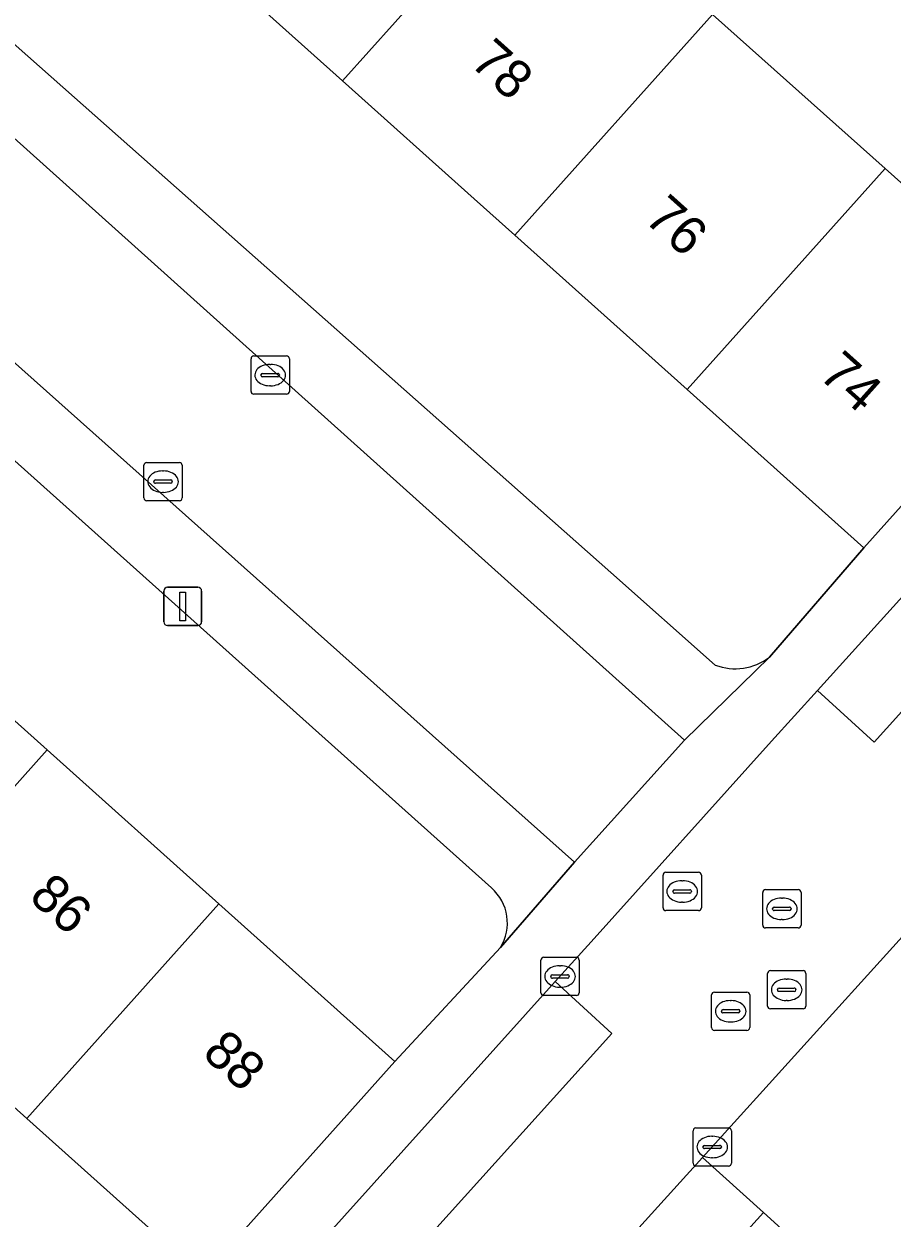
# Model space of a CAD drawing. Extents: x 159039 to 160102, y 381214 to 382524.
# Drawn here: x 159488.23 to 159510.93, y 381770.5 to 381801.71 of the extents above; entities that cross this region are included whole.
import ezdxf

# ---------------------------------------------------------------- set-up
doc = ezdxf.new("R2010")
doc.units = 0
for name, color, linetype in [('IMGEO_Erf', 7, 'Continuous'), ('IMGEO_Kolk', 7, 'Continuous'), ('IMGEO_Lichtmast', 7, 'Continuous'), ('IMGEO_Pand', 7, 'Continuous'), ('IMGEO_Pand_nummerreeks', 7, 'Continuous'), ('IMGEO_Parkeervlak_open', 7, 'Continuous'), ('IMGEO_Rijbaan_lokaal_open', 7, 'Continuous'), ('IMGEO_Rioolput', 7, 'Continuous'), ('IMGEO_Voetpad_open', 7, 'Continuous')]:
    doc.layers.add(name, color=color, linetype=linetype)

msp = doc.modelspace()

# ---------------------------------------------------------------- linework, layer by layer
at = {"layer": 'IMGEO_Erf'}
for points in [[(159500, 381819.846), (159495.918, 381815.23), (159500, 381811.574), (159503.673, 381808.285), (159503.333, 381807.906), (159503.451, 381807.8), (159507.898, 381803.818), (159506.231, 381801.957), (159510.743, 381797.929), (159515.367, 381793.8)], [(159501.065, 381796.188), (159500, 381797.141), (159496.559, 381800.223), (159491.947, 381804.353), (159492.348, 381804.8), (159489.145, 381807.669), (159485.386, 381803.473), (159485.533, 381803.343), (159487.723, 381801.404), (159503.573, 381787.369), (159506.301, 381784.953)], [(159500.454, 381779.131), (159482.304, 381795.376), (159480.705, 381796.807), (159481.965, 381798.214), (159482.586, 381798.907), (159481.405, 381800.01), (159470.575, 381788.888), (159462.202, 381778.537), (159461.61, 381777.805), (159456.183, 381771.095), (159456.944, 381770.48)], [(159507.718, 381785.16), (159510.188, 381788.017), (159505.57, 381792.153), (159501.065, 381796.188)], [(159473.576, 381783.985), (159474.721, 381785.263), (159472.259, 381787.467), (159476.579, 381792.296), (159479.045, 381790.089), (159479.818, 381790.953), (159480.34, 381790.486), (159484.353, 381786.758), (159488.841, 381782.739), (159493.329, 381778.719), (159497.93, 381774.598), (159500.688, 381777.572)], [(159492.904, 381768.986), (159488.306, 381773.102), (159483.817, 381777.121), (159481.709, 381774.763), (159477.218, 381778.778)]]:
    msp.add_lwpolyline(points, dxfattribs=at)
msp.add_lwpolyline([(159503.851, 381765.543), (159508.032, 381770.22), (159507.563, 381770.646), (159495.232, 381757.035), (159495.792, 381756.528), (159499.772, 381760.98), (159500, 381761.235)], close=True, dxfattribs=at)
for centre, radius, start, end in [((159506.824, 381786.328), 1.471, 249.1896, 307.4328), ((159499.643, 381778.212), 1.225, 328.5016, 48.5707)]:
    msp.add_arc(centre, radius, start, end, dxfattribs=at)
at = {"layer": 'IMGEO_Kolk'}
for p, q in [((159494.167, 381792.106), (159494.167, 381792.958)), ((159494.242, 381793.032), (159495.094, 381793.032)), ((159494.655, 381792.812), (159494.68, 381792.812)), ((159495.168, 381792.958), (159495.168, 381792.106)), ((159494.426, 381792.526), (159494.426, 381792.538)), ((159494.864, 381792.489), (159494.466, 381792.489)), ((159494.469, 381792.575), (159494.867, 381792.575)), ((159494.91, 381792.538), (159494.91, 381792.526)), ((159494.678, 381792.252), (159494.653, 381792.252)), ((159495.094, 381792.032), (159494.242, 381792.032)), ((159491.366, 381789.321), (159491.366, 381790.173)), ((159491.441, 381790.247), (159492.293, 381790.247)), ((159491.854, 381790.027), (159491.879, 381790.027)), ((159492.367, 381790.173), (159492.367, 381789.321)), ((159491.625, 381789.741), (159491.625, 381789.753)), ((159492.063, 381789.704), (159491.665, 381789.704)), ((159491.668, 381789.79), (159492.066, 381789.79)), ((159492.109, 381789.753), (159492.109, 381789.741)), ((159491.877, 381789.467), (159491.852, 381789.467)), ((159492.293, 381789.247), (159491.441, 381789.247)), ((159501.744, 381776.392), (159501.744, 381777.244)), ((159501.819, 381777.318), (159502.671, 381777.318)), ((159502.745, 381777.244), (159502.745, 381776.392)), ((159502.046, 381776.861), (159502.444, 381776.861)), ((159502.232, 381777.098), (159502.257, 381777.098)), ((159502.003, 381776.812), (159502.003, 381776.824)), ((159502.441, 381776.775), (159502.043, 381776.775)), ((159502.255, 381776.538), (159502.23, 381776.538)), ((159502.487, 381776.824), (159502.487, 381776.812)), ((159502.671, 381776.318), (159501.819, 381776.318)), ((159505.722, 381771.935), (159505.722, 381772.787)), ((159505.797, 381772.861), (159506.649, 381772.861)), ((159506.723, 381772.787), (159506.723, 381771.935)), ((159506.21, 381772.641), (159506.235, 381772.641)), ((159505.981, 381772.355), (159505.981, 381772.367)), ((159506.419, 381772.318), (159506.021, 381772.318)), ((159506.024, 381772.404), (159506.422, 381772.404)), ((159506.465, 381772.367), (159506.465, 381772.355)), ((159506.649, 381771.861), (159505.797, 381771.861)), ((159506.233, 381772.081), (159506.208, 381772.081))]:
    msp.add_line(p, q, dxfattribs=at)
for points in [[(159494.167, 381792.106), (159494.167, 381792.958)], [(159494.242, 381793.032), (159495.094, 381793.032)], [(159495.168, 381792.958), (159495.168, 381792.106)], [(159495.094, 381792.032), (159494.242, 381792.032)], [(159491.366, 381789.321), (159491.366, 381790.173)], [(159491.441, 381790.247), (159492.293, 381790.247)], [(159492.367, 381790.173), (159492.367, 381789.321)], [(159492.293, 381789.247), (159491.441, 381789.247)], [(159501.744, 381776.392), (159501.744, 381777.244)], [(159501.819, 381777.318), (159502.671, 381777.318)], [(159502.745, 381777.244), (159502.745, 381776.392)], [(159502.671, 381776.318), (159501.819, 381776.318)], [(159505.722, 381771.935), (159505.722, 381772.787)], [(159505.797, 381772.861), (159506.649, 381772.861)], [(159506.723, 381772.787), (159506.723, 381771.935)], [(159506.649, 381771.861), (159505.797, 381771.861)]]:
    msp.add_lwpolyline(points, dxfattribs=at)
for centre, radius, start, end in [((159494.244, 381792.956), 0.0765, 91.552, 178.448), ((159494.244, 381792.956), 0.0765, 91.552, 178.448), ((159495.092, 381792.956), 0.0765, 1.552, 88.448), ((159495.092, 381792.956), 0.0765, 1.552, 88.448), ((159494.466, 381792.535), 0.0403, 85.8775, 175.7526), ((159494.463, 381792.525), 0.0366, 178.938, 274.7102), ((159494.867, 381792.532), 0.043, 264.8664, 352.4533), ((159494.871, 381792.537), 0.0386, 1.7309, 96.639), ((159494.244, 381792.108), 0.0765, 181.552, 268.448), ((159494.244, 381792.108), 0.0765, 181.552, 268.448), ((159495.092, 381792.108), 0.0765, 271.552, 358.448), ((159495.092, 381792.108), 0.0765, 271.552, 358.448), ((159491.443, 381790.171), 0.0765, 91.552, 178.448), ((159491.443, 381790.171), 0.0765, 91.552, 178.448), ((159492.291, 381790.171), 0.0765, 1.552, 88.448), ((159492.291, 381790.171), 0.0765, 1.552, 88.448), ((159491.665, 381789.75), 0.0403, 85.8775, 175.7526), ((159491.662, 381789.74), 0.0366, 178.938, 274.7102), ((159492.066, 381789.747), 0.043, 264.8664, 352.4533), ((159492.07, 381789.752), 0.0386, 1.7309, 96.639), ((159491.443, 381789.323), 0.0765, 181.552, 268.448), ((159491.443, 381789.323), 0.0765, 181.552, 268.448), ((159492.291, 381789.323), 0.0765, 271.552, 358.448), ((159492.291, 381789.323), 0.0765, 271.552, 358.448), ((159501.821, 381777.242), 0.0765, 91.552, 178.448), ((159501.821, 381777.242), 0.0765, 91.552, 178.448), ((159502.669, 381777.242), 0.0765, 1.552, 88.448), ((159502.669, 381777.242), 0.0765, 1.552, 88.448), ((159502.043, 381776.821), 0.0403, 85.8775, 175.7526), ((159502.448, 381776.823), 0.0386, 1.7309, 96.639), ((159502.04, 381776.811), 0.0366, 178.938, 274.7102), ((159502.444, 381776.818), 0.043, 264.8664, 352.4533), ((159501.821, 381776.394), 0.0765, 181.552, 268.448), ((159501.821, 381776.394), 0.0765, 181.552, 268.448), ((159502.669, 381776.394), 0.0765, 271.552, 358.448), ((159502.669, 381776.394), 0.0765, 271.552, 358.448), ((159505.799, 381772.785), 0.0765, 91.552, 178.448), ((159505.799, 381772.785), 0.0765, 91.552, 178.448), ((159506.647, 381772.785), 0.0765, 1.552, 88.448), ((159506.647, 381772.785), 0.0765, 1.552, 88.448), ((159506.021, 381772.364), 0.0403, 85.8775, 175.7526), ((159506.018, 381772.354), 0.0366, 178.938, 274.7102), ((159506.422, 381772.361), 0.043, 264.8664, 352.4533), ((159506.426, 381772.366), 0.0386, 1.7309, 96.639), ((159505.799, 381771.937), 0.0765, 181.552, 268.448), ((159505.799, 381771.937), 0.0765, 181.552, 268.448), ((159506.647, 381771.937), 0.0765, 271.552, 358.448), ((159506.647, 381771.937), 0.0765, 271.552, 358.448)]:
    msp.add_arc(centre, radius, start, end, dxfattribs=at)
for centre, major_axis, ratio, start_param, end_param in [((159494.654, 381792.532), (-0.387, 0.002), 0.722429, 4.712389, 7.853982), ((159494.679, 381792.532), (-0.39, 0.002), 0.717154, 1.570796, 4.712389), ((159491.853, 381789.747), (-0.387, 0.002), 0.722429, 4.712389, 7.853982), ((159491.878, 381789.747), (-0.39, 0.002), 0.717154, 1.570796, 4.712389), ((159502.231, 381776.818), (-0.387, 0.002), 0.722429, 4.712389, 7.853982), ((159502.256, 381776.818), (-0.39, 0.002), 0.717154, 1.570796, 4.712389), ((159506.209, 381772.361), (-0.387, 0.002), 0.722429, 4.712389, 7.853982), ((159506.234, 381772.361), (-0.39, 0.002), 0.717154, 1.570796, 4.712389)]:
    msp.add_ellipse(centre, major_axis=major_axis, ratio=ratio, start_param=start_param, end_param=end_param, dxfattribs=at)
at = {"layer": 'IMGEO_Lichtmast'}
for p, q in [((159491.886, 381786.086), (159491.886, 381786.886)), ((159491.886, 381786.886), (159491.886, 381786.086)), ((159491.986, 381786.986), (159492.776, 381786.986)), ((159492.776, 381786.986), (159491.986, 381786.986)), ((159492.876, 381786.886), (159492.876, 381786.086)), ((159492.876, 381786.086), (159492.876, 381786.886)), ((159492.776, 381785.986), (159491.986, 381785.986)), ((159491.986, 381785.986), (159492.776, 381785.986))]:
    msp.add_line(p, q, dxfattribs=at)
msp.add_lwpolyline([(159492.306, 381786.861), (159492.456, 381786.861), (159492.456, 381786.111), (159492.306, 381786.111), (159492.306, 381786.861)], dxfattribs=at)
for centre, start, end in [((159491.986, 381786.886), 90, 180), ((159491.986, 381786.886), 90, 180), ((159492.776, 381786.886), 0, 90), ((159492.776, 381786.886), 360, 90), ((159491.986, 381786.086), 180, 270), ((159491.986, 381786.086), 180, 270), ((159492.776, 381786.086), 270, 0), ((159492.776, 381786.086), 270, 0)]:
    msp.add_arc(centre, 0.1, start, end, dxfattribs=at)
at = {"layer": 'IMGEO_Pand'}
for points in [[(159496.559, 381800.223), (159500, 381804.065), (159501.736, 381806.004), (159503.451, 381807.8), (159503.333, 381807.906), (159503.673, 381808.285), (159500, 381811.574), (159495.918, 381815.23), (159489.145, 381807.669), (159492.348, 381804.8), (159491.947, 381804.353)], [(159496.559, 381800.223), (159500, 381797.141), (159501.065, 381796.188), (159506.231, 381801.957), (159507.898, 381803.818), (159503.451, 381807.8), (159501.736, 381806.004), (159500, 381804.065)], [(159510.743, 381797.929), (159506.231, 381801.957), (159501.065, 381796.188), (159505.57, 381792.153)], [(159510.743, 381797.929), (159505.57, 381792.153), (159510.188, 381788.017), (159515.367, 381793.8)], [(159488.841, 381782.739), (159484.353, 381786.758), (159479.328, 381781.139), (159477.218, 381778.778), (159481.709, 381774.763), (159483.817, 381777.121)], [(159493.329, 381778.719), (159488.841, 381782.739), (159483.817, 381777.121), (159488.306, 381773.102)], [(159493.329, 381778.719), (159488.306, 381773.102), (159492.904, 381768.986), (159497.93, 381774.598)]]:
    msp.add_lwpolyline(points, close=True, dxfattribs=at)
at = {"layer": 'IMGEO_Parkeervlak_open'}
for points in [[(159520.178, 381796.676), (159508.977, 381784.292), (159510.46, 381782.935), (159521.64, 381795.325)], [(159502.12, 381776.684), (159490.252, 381763.489), (159491.718, 381762.164), (159503.595, 381775.326)]]:
    msp.add_lwpolyline(points, close=True, dxfattribs=at)
msp.add_lwpolyline([(159491.728, 381753.174), (159494.123, 381755.811), (159495.232, 381757.035), (159507.563, 381770.646), (159505.968, 381772.09), (159492.635, 381757.366), (159490.12, 381754.579), (159488.97, 381753.299), (159485.771, 381749.749), (159479.731, 381743.038)], dxfattribs=at)
at = {"layer": 'IMGEO_Rijbaan_lokaal_open'}
msp.add_lwpolyline([(159492.635, 381757.366), (159505.968, 381772.09), (159511.108, 381777.766), (159533.847, 381802.894), (159530.884, 381805.57), (159529.238, 381803.745), (159527.763, 381805.071), (159527.126, 381804.363), (159521.088, 381797.682), (159520.178, 381796.676), (159521.64, 381795.325), (159510.46, 381782.935), (159508.977, 381784.292), (159507.773, 381782.961), (159503.057, 381777.726), (159502.12, 381776.684), (159503.595, 381775.326), (159491.718, 381762.164)], dxfattribs=at)
msp.add_lwpolyline([(159486.504, 381800.037), (159484.913, 381801.464), (159484.376, 381800.892), (159482.586, 381798.907), (159481.965, 381798.214), (159483.564, 381796.789), (159502.62, 381779.807), (159504.061, 381781.401), (159505.502, 381782.995)], close=True, dxfattribs=at)
at = {"layer": 'IMGEO_Rioolput'}
for p, q in [((159504.937, 381778.613), (159504.937, 381779.465)), ((159505.012, 381779.539), (159505.864, 381779.539)), ((159505.938, 381779.465), (159505.938, 381778.613)), ((159505.196, 381779.033), (159505.196, 381779.045)), ((159505.239, 381779.082), (159505.637, 381779.082)), ((159505.425, 381779.319), (159505.45, 381779.319)), ((159505.68, 381779.045), (159505.68, 381779.033)), ((159507.618, 381779.085), (159508.47, 381779.085)), ((159505.634, 381778.996), (159505.236, 381778.996)), ((159505.448, 381778.759), (159505.423, 381778.759)), ((159507.543, 381778.159), (159507.543, 381779.011)), ((159508.031, 381778.865), (159508.056, 381778.865)), ((159508.544, 381779.011), (159508.544, 381778.159)), ((159505.864, 381778.539), (159505.012, 381778.539)), ((159507.802, 381778.579), (159507.802, 381778.591)), ((159508.24, 381778.542), (159507.842, 381778.542)), ((159507.845, 381778.628), (159508.243, 381778.628)), ((159508.286, 381778.591), (159508.286, 381778.579)), ((159508.47, 381778.085), (159507.618, 381778.085)), ((159508.054, 381778.305), (159508.029, 381778.305)), ((159507.669, 381776.044), (159507.669, 381776.896)), ((159507.744, 381776.97), (159508.596, 381776.97)), ((159508.67, 381776.896), (159508.67, 381776.044)), ((159508.157, 381776.75), (159508.182, 381776.75)), ((159506.204, 381775.481), (159506.204, 381776.333)), ((159506.279, 381776.407), (159507.131, 381776.407)), ((159507.205, 381776.333), (159507.205, 381775.481)), ((159507.928, 381776.464), (159507.928, 381776.476)), ((159508.366, 381776.427), (159507.968, 381776.427)), ((159507.971, 381776.513), (159508.369, 381776.513)), ((159508.412, 381776.476), (159508.412, 381776.464)), ((159506.463, 381775.901), (159506.463, 381775.913)), ((159506.506, 381775.95), (159506.904, 381775.95)), ((159506.692, 381776.187), (159506.717, 381776.187)), ((159506.947, 381775.913), (159506.947, 381775.901)), ((159508.596, 381775.97), (159507.744, 381775.97)), ((159508.18, 381776.19), (159508.155, 381776.19)), ((159506.901, 381775.864), (159506.503, 381775.864)), ((159506.715, 381775.627), (159506.69, 381775.627)), ((159507.131, 381775.407), (159506.279, 381775.407))]:
    msp.add_line(p, q, dxfattribs=at)
for points in [[(159504.937, 381778.613), (159504.937, 381779.465)], [(159505.012, 381779.539), (159505.864, 381779.539)], [(159505.938, 381779.465), (159505.938, 381778.613)], [(159507.618, 381779.085), (159508.47, 381779.085)], [(159507.543, 381778.159), (159507.543, 381779.011)], [(159508.544, 381779.011), (159508.544, 381778.159)], [(159505.864, 381778.539), (159505.012, 381778.539)], [(159508.47, 381778.085), (159507.618, 381778.085)], [(159507.669, 381776.044), (159507.669, 381776.896)], [(159507.744, 381776.97), (159508.596, 381776.97)], [(159508.67, 381776.896), (159508.67, 381776.044)], [(159506.204, 381775.481), (159506.204, 381776.333)], [(159506.279, 381776.407), (159507.131, 381776.407)], [(159507.205, 381776.333), (159507.205, 381775.481)], [(159508.596, 381775.97), (159507.744, 381775.97)], [(159507.131, 381775.407), (159506.279, 381775.407)]]:
    msp.add_lwpolyline(points, dxfattribs=at)
for centre, radius, start, end in [((159505.014, 381779.463), 0.0765, 91.552, 178.448), ((159505.014, 381779.463), 0.0765, 91.552, 178.448), ((159505.862, 381779.463), 0.0765, 1.552, 88.448), ((159505.862, 381779.463), 0.0765, 1.552, 88.448), ((159505.236, 381779.042), 0.0403, 85.8775, 175.7526), ((159505.233, 381779.032), 0.0366, 178.938, 274.7102), ((159505.637, 381779.039), 0.043, 264.8664, 352.4533), ((159505.641, 381779.044), 0.0386, 1.7309, 96.639), ((159507.62, 381779.009), 0.0765, 91.552, 178.448), ((159507.62, 381779.009), 0.0765, 91.552, 178.448), ((159508.468, 381779.009), 0.0765, 1.552, 88.448), ((159508.468, 381779.009), 0.0765, 1.552, 88.448), ((159505.014, 381778.615), 0.0765, 181.552, 268.448), ((159505.014, 381778.615), 0.0765, 181.552, 268.448), ((159505.862, 381778.615), 0.0765, 271.552, 358.448), ((159505.862, 381778.615), 0.0765, 271.552, 358.448), ((159507.842, 381778.588), 0.0403, 85.8775, 175.7526), ((159507.839, 381778.578), 0.0366, 178.938, 274.7102), ((159508.243, 381778.585), 0.043, 264.8664, 352.4533), ((159508.247, 381778.59), 0.0386, 1.7309, 96.639), ((159507.62, 381778.161), 0.0765, 181.552, 268.448), ((159507.62, 381778.161), 0.0765, 181.552, 268.448), ((159508.468, 381778.161), 0.0765, 271.552, 358.448), ((159508.468, 381778.161), 0.0765, 271.552, 358.448), ((159507.746, 381776.894), 0.0765, 91.552, 178.448), ((159507.746, 381776.894), 0.0765, 91.552, 178.448), ((159508.594, 381776.894), 0.0765, 1.552, 88.448), ((159508.594, 381776.894), 0.0765, 1.552, 88.448), ((159506.281, 381776.331), 0.0765, 91.552, 178.448), ((159506.281, 381776.331), 0.0765, 91.552, 178.448), ((159507.129, 381776.331), 0.0765, 1.552, 88.448), ((159507.129, 381776.331), 0.0765, 1.552, 88.448), ((159507.968, 381776.473), 0.0403, 85.8775, 175.7526), ((159507.965, 381776.463), 0.0366, 178.938, 274.7102), ((159508.369, 381776.47), 0.043, 264.8664, 352.4533), ((159508.373, 381776.475), 0.0386, 1.7309, 96.639), ((159506.503, 381775.91), 0.0403, 85.8775, 175.7526), ((159506.5, 381775.9), 0.0366, 178.938, 274.7102), ((159506.904, 381775.907), 0.043, 264.8664, 352.4533), ((159506.908, 381775.912), 0.0386, 1.7309, 96.639), ((159507.746, 381776.046), 0.0765, 181.552, 268.448), ((159507.746, 381776.046), 0.0765, 181.552, 268.448), ((159508.594, 381776.046), 0.0765, 271.552, 358.448), ((159508.594, 381776.046), 0.0765, 271.552, 358.448), ((159506.281, 381775.483), 0.0765, 181.552, 268.448), ((159506.281, 381775.483), 0.0765, 181.552, 268.448), ((159507.129, 381775.483), 0.0765, 271.552, 358.448), ((159507.129, 381775.483), 0.0765, 271.552, 358.448)]:
    msp.add_arc(centre, radius, start, end, dxfattribs=at)
for centre, major_axis, ratio, start_param, end_param in [((159505.424, 381779.039), (-0.387, 0.002), 0.722429, 4.712389, 7.853982), ((159505.449, 381779.039), (-0.39, 0.002), 0.717154, 1.570796, 4.712389), ((159508.03, 381778.585), (-0.387, 0.002), 0.722429, 4.712389, 7.853982), ((159508.055, 381778.585), (-0.39, 0.002), 0.717154, 1.570796, 4.712389), ((159508.156, 381776.47), (-0.387, 0.002), 0.722429, 4.712389, 7.853982), ((159508.181, 381776.47), (-0.39, 0.002), 0.717154, 1.570796, 4.712389), ((159506.691, 381775.907), (-0.387, 0.002), 0.722429, 4.712389, 7.853982), ((159506.716, 381775.907), (-0.39, 0.002), 0.717154, 1.570796, 4.712389)]:
    msp.add_ellipse(centre, major_axis=major_axis, ratio=ratio, start_param=start_param, end_param=end_param, dxfattribs=at)
at = {"layer": 'IMGEO_Voetpad_open'}
for points in [[(159531.369, 381820.579), (159535.953, 381816.449), (159530.745, 381810.669), (159525.705, 381805.18), (159523.463, 381802.692), (159522.458, 381801.62), (159520.54, 381799.492), (159520.024, 381798.919), (159515.367, 381793.8), (159510.188, 381788.017), (159507.718, 381785.16), (159505.502, 381782.995), (159504.061, 381781.401), (159502.62, 381779.807), (159500.688, 381777.572), (159497.93, 381774.598), (159492.904, 381768.986), (159488.189, 381763.723), (159485.777, 381761.03), (159484.576, 381759.714), (159477.556, 381752.021), (159475.747, 381750), (159472.466, 381746.336), (159474.244, 381745.244)], [(159484.621, 381757.257), (159486.874, 381759.764), (159489.416, 381762.559), (159490.252, 381763.489), (159502.12, 381776.684), (159503.057, 381777.726), (159507.773, 381782.961), (159508.977, 381784.292), (159520.178, 381796.676), (159521.088, 381797.682), (159527.126, 381804.363), (159527.763, 381805.071), (159535.61, 381813.79)], [(159487.723, 381801.404), (159485.533, 381803.343), (159484.913, 381801.464), (159486.504, 381800.037), (159505.502, 381782.995), (159507.718, 381785.16)], [(159506.301, 381784.953), (159503.573, 381787.369), (159487.723, 381801.404)], [(159483.564, 381796.789), (159481.965, 381798.214), (159480.705, 381796.807), (159482.304, 381795.376), (159500.454, 381779.131)], [(159500.688, 381777.572), (159502.62, 381779.807), (159483.564, 381796.789)], [(159511.108, 381777.766), (159505.968, 381772.09), (159507.563, 381770.646), (159508.032, 381770.22), (159514.64, 381764.31), (159514.996, 381764.721), (159517.222, 381767.108), (159514.446, 381769.582)]]:
    msp.add_lwpolyline(points, dxfattribs=at)
for centre, radius, start, end in [((159506.824, 381786.328), 1.471, 249.1896, 307.4328), ((159499.643, 381778.212), 1.225, 328.5016, 48.5707)]:
    msp.add_arc(centre, radius, start, end, dxfattribs=at)

# ---------------------------------------------------------------- texts
at = {"layer": 'IMGEO_Pand_nummerreeks'}
for s, rotation, p in [('78', 318.1535, (159499.855, 381800.653)), ('76', 318.1535, (159504.413, 381796.571)), ('74', 318.1535, (159508.974, 381792.487)), ('86', 317.9182, (159488.326, 381778.851)), ('88', 317.9182, (159492.856, 381774.76))]:
    msp.add_text(s, height=1, rotation=rotation, dxfattribs=at).set_placement(p)

doc.saveas('drawing.dxf')
